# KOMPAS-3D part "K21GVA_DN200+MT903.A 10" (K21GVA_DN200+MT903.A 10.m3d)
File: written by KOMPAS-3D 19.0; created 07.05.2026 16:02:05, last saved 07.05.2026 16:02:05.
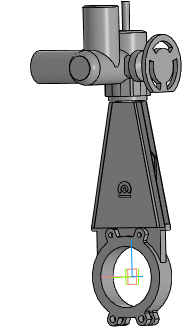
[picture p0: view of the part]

Document properties: Автор: Энергия; Полное имя файла: ..\K21GVA_DN50-DN1000+MT903.A\K21GVA_DN200+MT903.A 10.a3d

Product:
- Part/product: K21GVA_DN200+MT903.A 10
    Масса: 104.975

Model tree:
1. Операция без истории:1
